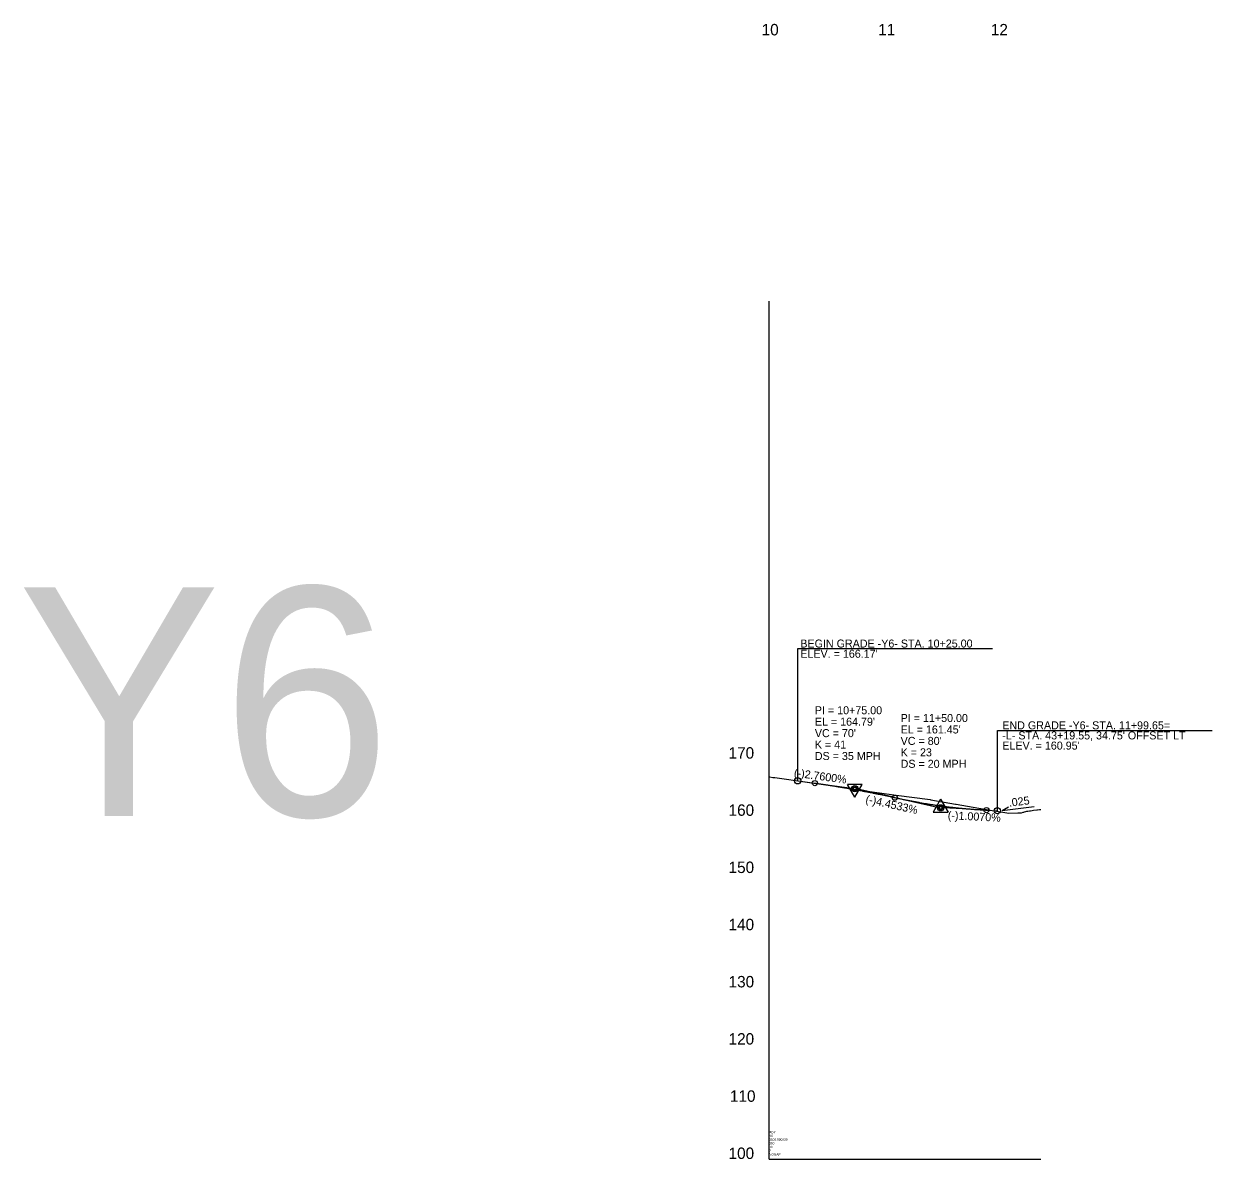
# Model space of a CAD drawing. Extents: x 1778432 to 1784301, y 601022 to 621789.
# Drawn here: x 1779491 to 1780530, y 611039 to 612032 of the extents above; entities that cross this region are included whole.
import ezdxf

# ---------------------------------------------------------------- set-up
doc = ezdxf.new("R2010")
doc.units = 0
for name, color, linetype in [('Exist Profile Cell', 7, 'Continuous'), ('Exist Vertical Profile Ground Line', 7, 'Continuous'), ('Exist Vertical Profile Horizontal Axis Label Major', 7, 'Continuous'), ('Exist Vertical Profile Vertical Axis Label', 7, 'Continuous'), ('Prop PFL Text', 7, 'Continuous'), ('Prop PFL VPI Symbol CELL', 7, 'Continuous'), ('Prop Vertical Profile Curve Label', 7, 'Continuous'), ('Prop Vertical Profile Grade', 7, 'Continuous'), ('Prop Vertical Profile Grade Label', 7, 'Continuous'), ('Prop VPI Label', 7, 'Continuous')]:
    doc.layers.add(name, color=color, linetype=linetype)

msp = doc.modelspace()

# ---------------------------------------------------------------- linework, layer by layer
at = {"layer": 'Exist Profile Cell'}
for q in [(1780143, 611789.2), (1780380.5, 611039.2), (1780143, 611039.2)]:
    msp.add_line((1780143, 611039.2), q, dxfattribs=at)
at = {"layer": 'Exist Vertical Profile Ground Line'}
msp.add_lwpolyline([(1780143.5, 611373.4), (1780146.4, 611373), (1780148.1, 611372.8), (1780176.4, 611368.9), (1780180, 611368.3), (1780203, 611364.9), (1780207.2, 611364.3), (1780233, 611360.5), (1780252.2, 611357.9), (1780254.2, 611357.6), (1780283.7, 611353.6), (1780284.4, 611353.5), (1780306.1, 611349.6), (1780306.6, 611349.6), (1780336.2, 611344.3), (1780350.8, 611342), (1780352.7, 611341.8), (1780360.4, 611342), (1780363.6, 611341.9), (1780365.2, 611342.5), (1780365.8, 611342.7), (1780366.4, 611342.9), (1780367.4, 611343.2), (1780368.2, 611343.4), (1780368.7, 611343.5), (1780369.1, 611343.5), (1780370.8, 611343.8), (1780371.6, 611343.9), (1780372.9, 611344.2), (1780374.2, 611344.3), (1780377, 611344.6), (1780377.6, 611344.7), (1780379.4, 611344.8), (1780380, 611344.8), (1780380.5, 611344.8)], dxfattribs=at)
at = {"layer": 'Prop PFL VPI Symbol CELL'}
for p, q in [((1780218, 611355.7), (1780211.5, 611366.9)), ((1780224.4, 611366.9), (1780211.5, 611366.9)), ((1780218, 611355.7), (1780224.4, 611366.9)), ((1780293, 611353.9), (1780286.5, 611342.7)), ((1780293, 611353.9), (1780299.5, 611342.7)), ((1780286.5, 611342.7), (1780299.5, 611342.7))]:
    msp.add_line(p, q, dxfattribs=at)
for centre, radius in [((1780218, 611363.2), 1.75), ((1780218, 611363.2), 1.2), ((1780293, 611346.4), 1.75), ((1780293, 611346.4), 1.2)]:
    msp.add_circle(centre, radius, dxfattribs=at)
at = {"layer": 'Prop Vertical Profile Curve Label'}
for centre in [(1780183, 611368), (1780253, 611355.3), (1780253, 611355.3), (1780333, 611344.4)]:
    msp.add_circle(centre, 2.25, dxfattribs=at)
at = {"layer": 'Prop Vertical Profile Grade'}
for p, q in [((1780168, 611370), (1780183, 611368)), ((1780333, 611344.4), (1780342.6, 611343.9))]:
    msp.add_line(p, q, dxfattribs=at)
for points in [[(1780183, 611368), (1780184.4, 611367.8), (1780185.8, 611367.6), (1780187.2, 611367.4), (1780188.6, 611367.2), (1780190, 611367), (1780191.4, 611366.8), (1780192.8, 611366.6), (1780194.2, 611366.4), (1780195.6, 611366.1), (1780197, 611365.9), (1780198.4, 611365.7), (1780199.8, 611365.5), (1780201.2, 611365.3), (1780202.6, 611365), (1780204, 611364.8), (1780205.4, 611364.6), (1780206.8, 611364.4), (1780208.2, 611364.1), (1780209.6, 611363.9), (1780211, 611363.6), (1780212.4, 611363.4), (1780213.8, 611363.2), (1780215.2, 611362.9), (1780216.6, 611362.7), (1780218, 611362.4), (1780219.4, 611362.2), (1780220.8, 611361.9), (1780222.2, 611361.6), (1780223.6, 611361.4), (1780225, 611361.1), (1780226.4, 611360.8), (1780227.8, 611360.6), (1780229.2, 611360.3), (1780230.6, 611360), (1780232, 611359.8), (1780233.4, 611359.5), (1780234.8, 611359.2), (1780236.2, 611358.9), (1780237.6, 611358.6), (1780239, 611358.3), (1780240.4, 611358.1), (1780241.8, 611357.8), (1780243.2, 611357.5), (1780244.6, 611357.2), (1780246, 611356.9), (1780247.4, 611356.6), (1780248.8, 611356.3), (1780250.2, 611356), (1780251.6, 611355.7), (1780253, 611355.3)], [(1780253, 611355.3), (1780254.6, 611355), (1780256.2, 611354.6), (1780257.8, 611354.3), (1780259.4, 611354), (1780261, 611353.6), (1780262.6, 611353.3), (1780264.2, 611353), (1780265.8, 611352.7), (1780267.4, 611352.4), (1780269, 611352.1), (1780270.6, 611351.8), (1780272.2, 611351.5), (1780273.8, 611351.2), (1780275.4, 611350.9), (1780277, 611350.6), (1780278.6, 611350.3), (1780280.2, 611350.1), (1780281.8, 611349.8), (1780283.4, 611349.6), (1780285, 611349.3), (1780286.6, 611349.1), (1780288.2, 611348.8), (1780289.8, 611348.6), (1780291.4, 611348.4), (1780293, 611348.2), (1780294.6, 611347.9), (1780296.2, 611347.7), (1780297.8, 611347.5), (1780299.4, 611347.3), (1780301, 611347.1), (1780302.6, 611346.9), (1780304.2, 611346.8), (1780305.8, 611346.6), (1780307.4, 611346.4), (1780309, 611346.2), (1780310.6, 611346.1), (1780312.2, 611345.9), (1780313.8, 611345.8), (1780315.4, 611345.6), (1780317, 611345.5), (1780318.6, 611345.4), (1780320.2, 611345.2), (1780321.8, 611345.1), (1780323.4, 611345), (1780325, 611344.9), (1780326.6, 611344.8), (1780328.2, 611344.7), (1780329.8, 611344.6), (1780331.4, 611344.5), (1780333, 611344.4)]]:
    msp.add_spline(points, degree=3, dxfattribs=at)
at = {"layer": 'Prop VPI Label'}
for p, q in [((1780168, 611370), (1780168, 611485.6)), ((1780168, 611485.6), (1780338.3, 611485.6)), ((1780342.6, 611343.9), (1780342.6, 611413.9)), ((1780342.6, 611413.9), (1780530.4, 611413.9)), ((1780183, 611368), (1780215.2, 611363.5)), ((1780253, 611355.3), (1780220.6, 611362.6)), ((1780253, 611355.3), (1780290.3, 611347)), ((1780333, 611344.4), (1780295.7, 611346.3)), ((1780333, 611344.4), (1780295.7, 611346.3)), ((1780346.7, 611344.1), (1780374.7, 611347.6)), ((1780346.7, 611344.1), (1780352.4, 611347.2))]:
    msp.add_line(p, q, dxfattribs=at)
for centre in [(1780168, 611370), (1780218, 611363.2), (1780293, 611346.4), (1780342.6, 611343.9)]:
    msp.add_circle(centre, 2.75, dxfattribs=at)

# ---------------------------------------------------------------- texts
at = {"layer": 'Exist Profile Cell'}
for s, p in [('Y6', (1780143, 611058.7)), ('RDY', (1780143, 611061.9)), ('1000.000000', (1780143, 611055.4)), ('100', (1780143, 611052.2)), ('10', (1780143, 611048.9)), ('2', (1780143, 611045.7)), ('NOGAP', (1780143, 611042.4))]:
    msp.add_text(s, height=2, dxfattribs=at).set_placement(p)
at = {"layer": 'Exist Vertical Profile Horizontal Axis Label Major'}
for s, p in [('10', (1780136.5, 612021.7)), ('10', (1780136.5, 612021.7)), ('11', (1780238.4, 612021.7)), ('11', (1780238.4, 612021.7)), ('12', (1780336.9, 612021.7)), ('12', (1780336.9, 612021.7))]:
    msp.add_text(s, height=10, dxfattribs=at).set_placement(p)
at = {"layer": 'Exist Vertical Profile Vertical Axis Label'}
for s, p in [('170', (1780107.6, 611389.4)), ('160', (1780107.6, 611339.4)), ('150', (1780107.6, 611289.4)), ('140', (1780107.6, 611239.4)), ('130', (1780107.6, 611189.4)), ('120', (1780107.6, 611139.4)), ('110', (1780108.8, 611089.4)), ('100', (1780107.6, 611039.4))]:
    msp.add_text(s, height=10, dxfattribs=at).set_placement(p)
at = {"layer": 'Prop PFL Text'}
msp.add_text('Y6', height=200, dxfattribs=at).set_placement((1779485.5, 611339.2))
at = {"layer": 'Prop Vertical Profile Curve Label'}
for s, p in [("VC = 70'", (1780183, 611408.2)), ('K = 41', (1780183, 611398.2)), ("VC = 80'", (1780258, 611401.4)), ('DS = 35 MPH', (1780183, 611388.2)), ('K = 23', (1780258, 611391.4)), ('DS = 20 MPH', (1780258, 611381.4))]:
    msp.add_text(s, height=7, dxfattribs=at).set_placement(p)
at = {"layer": 'Prop Vertical Profile Grade Label'}
for s, rotation, p in [('(-)2.7600%', 352.1501, (1780164.4, 611373.8)), ('(-)4.4533%', 347.4276, (1780226.9, 611350.9)), ('.025', 7.125, (1780353, 611347.3)), ('(-)1.0070%', 357.1376, (1780299.1, 611336.5))]:
    msp.add_text(s, height=7, rotation=rotation, dxfattribs=at).set_placement(p)
at = {"layer": 'Prop VPI Label'}
for s, p in [('BEGIN GRADE -Y6- STA. 10+25.00', (1780170.3, 611486.5)), ("ELEV. = 166.17'", (1780170.3, 611477.6)), ('PI = 10+75.00', (1780183, 611428.2)), ("EL = 164.79'", (1780183, 611418.2)), ('PI = 11+50.00', (1780258, 611421.4)), ("EL = 161.45'", (1780258, 611411.4)), ("-L- STA. 43+19.55, 34.75' OFFSET LT", (1780346.9, 611406.2)), ('END GRADE -Y6- STA. 11+99.65=', (1780346.9, 611415)), ("ELEV. = 160.95'", (1780346.9, 611397.3))]:
    msp.add_text(s, height=7, dxfattribs=at).set_placement(p)

doc.saveas('drawing.dxf')
